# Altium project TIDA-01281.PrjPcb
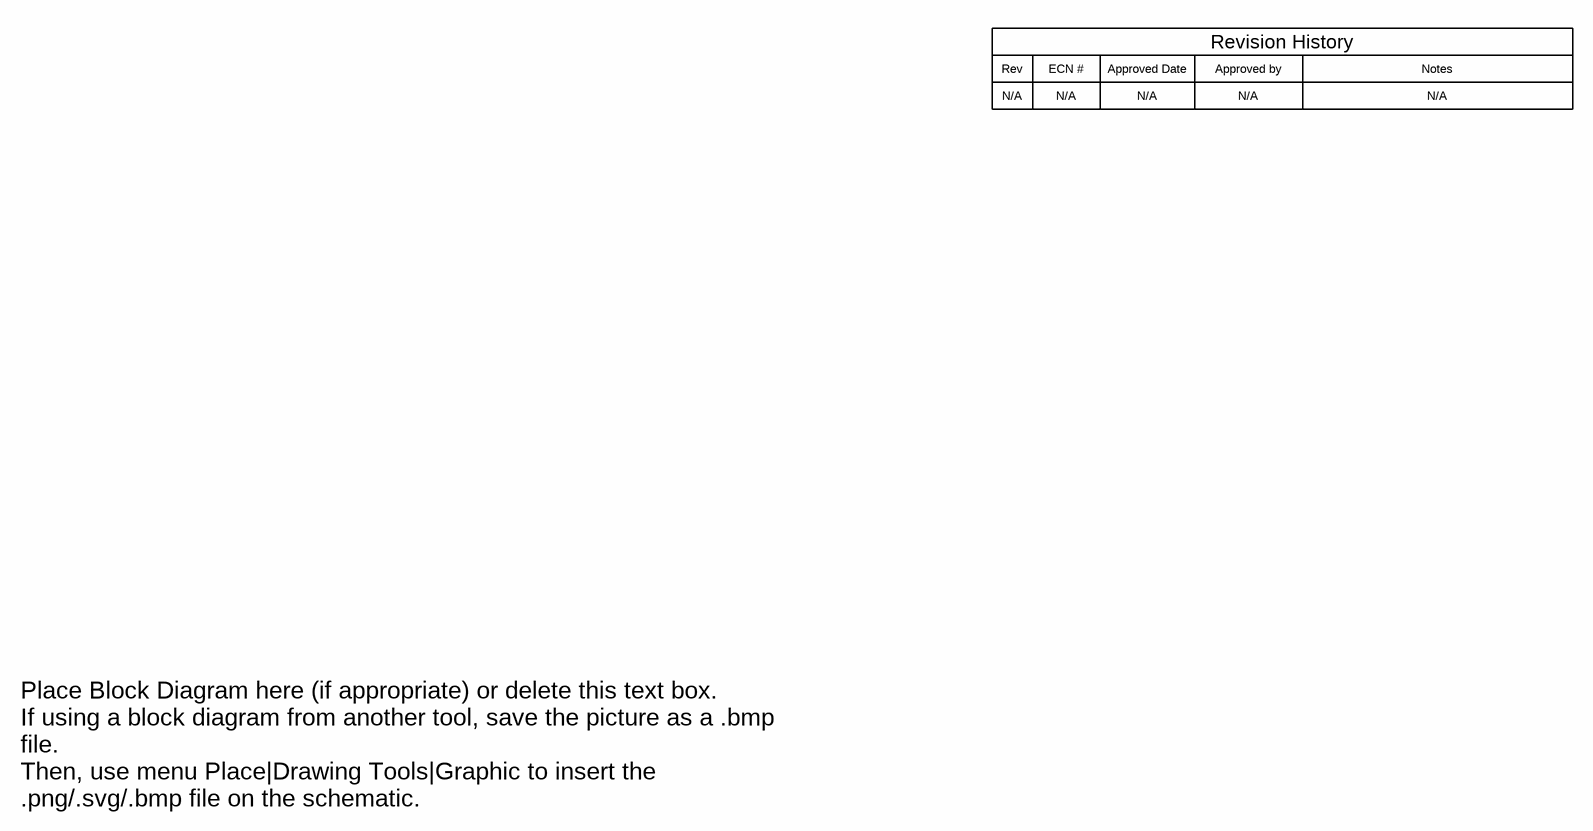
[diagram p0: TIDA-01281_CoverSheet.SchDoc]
TID: TIDA-01281; TechSupport: http://www.ti.com/support; SCH_Rev: E1; PRJ_Title: Communication Module; PRJ_Number: TIDA-01281; PRJ_Engineer: Ramkumar S; PRJ_Customer: Public Release; PCB_Rev: E1; PCB_Layout: Akshay Labhe; EVM_Orderable: N/A; CopyrightYear: 2016
3 sheets, 110 parts. Net scope: global (net labels, ports and power ports of the same name join across sheets).
Board file: TIDA-01281.PcbDoc
Sheets:
  TIDA-01281_CoverSheet.SchDoc
  TIDA-01281_Sheet1.SchDoc
  TIDA-01281_Hardware.SchDoc

## Sheet TIDA-01281_CoverSheet.SchDoc
size 431 x 279 mm; Date: Not shown in title block; ApprovedBy: Not shown in title block; CheckedBy: Not shown in title block; Author: Not shown in title block; CompanyName: Not shown in title block; DrawnBy: Ramkumar S; Engineer: Not shown in title block; Organization: Not shown in title block; Address1: Not shown in title block; Address2: Not shown in title block; Address3: Not shown in title block; Address4: Not shown in title block; DocumentNumber: 1; Revision: Use project parameter SCH_Rev; SheetNumber: 1; SheetTotal: 3; PageSetup: Record=PageOptions¦CenterHorizontal=True¦CenterVertical=True¦PrintScale=1.00¦XCorrection=1.00¦YCorrection=1.00¦PrintKind=0¦BorderSize=5000000¦LeftOffset=0¦BottomOffset=0¦Orientation=2¦PaperLength=1000¦PaperWidth=1000¦Scale=100¦PaperSource=15¦PrintQuality=600¦MediaType=1¦DitherType=10¦PaperKind=Letter¦PrintScaleMode=1

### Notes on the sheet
- Rev
- N/A
- ECN #
- Approved Date
- Approved by
- Revision History
- Notes
- Place Block Diagram here (if appropriate) or delete this text box.
  If using a block diagram from another tool, save the picture as a .bmp file.
  Then, use menu Place|Drawing Tools|Graphic to insert the .png/.svg/.bmp file on the schematic.

## Sheet TIDA-01281_Sheet1.SchDoc
size 431 x 279 mm; Date: Not shown in title block; ApprovedBy: Not shown in title block; CheckedBy: Not shown in title block; Author: Not shown in title block; CompanyName: Not shown in title block; DrawnBy: Ramkumar S; Engineer: Not shown in title block; Organization: Not shown in title block; Address1: Not shown in title block; Address2: Not shown in title block; Address3: Not shown in title block; Address4: Not shown in title block; DocumentNumber: 1; Revision: Use project parameter SCH_Rev; SheetNumber: 2; SheetTotal: 3; PageSetup: Record=PageOptions¦CenterHorizontal=True¦CenterVertical=True¦PrintScale=1.00¦XCorrection=1.00¦YCorrection=1.00¦PrintKind=0¦BorderSize=5000000¦LeftOffset=0¦BottomOffset=0¦Orientation=2¦PaperLength=1000¦PaperWidth=1000¦Scale=100¦PaperSource=15¦PrintQuality=600¦MediaType=1¦DitherType=10¦PaperKind=Letter¦PrintScaleMode=1
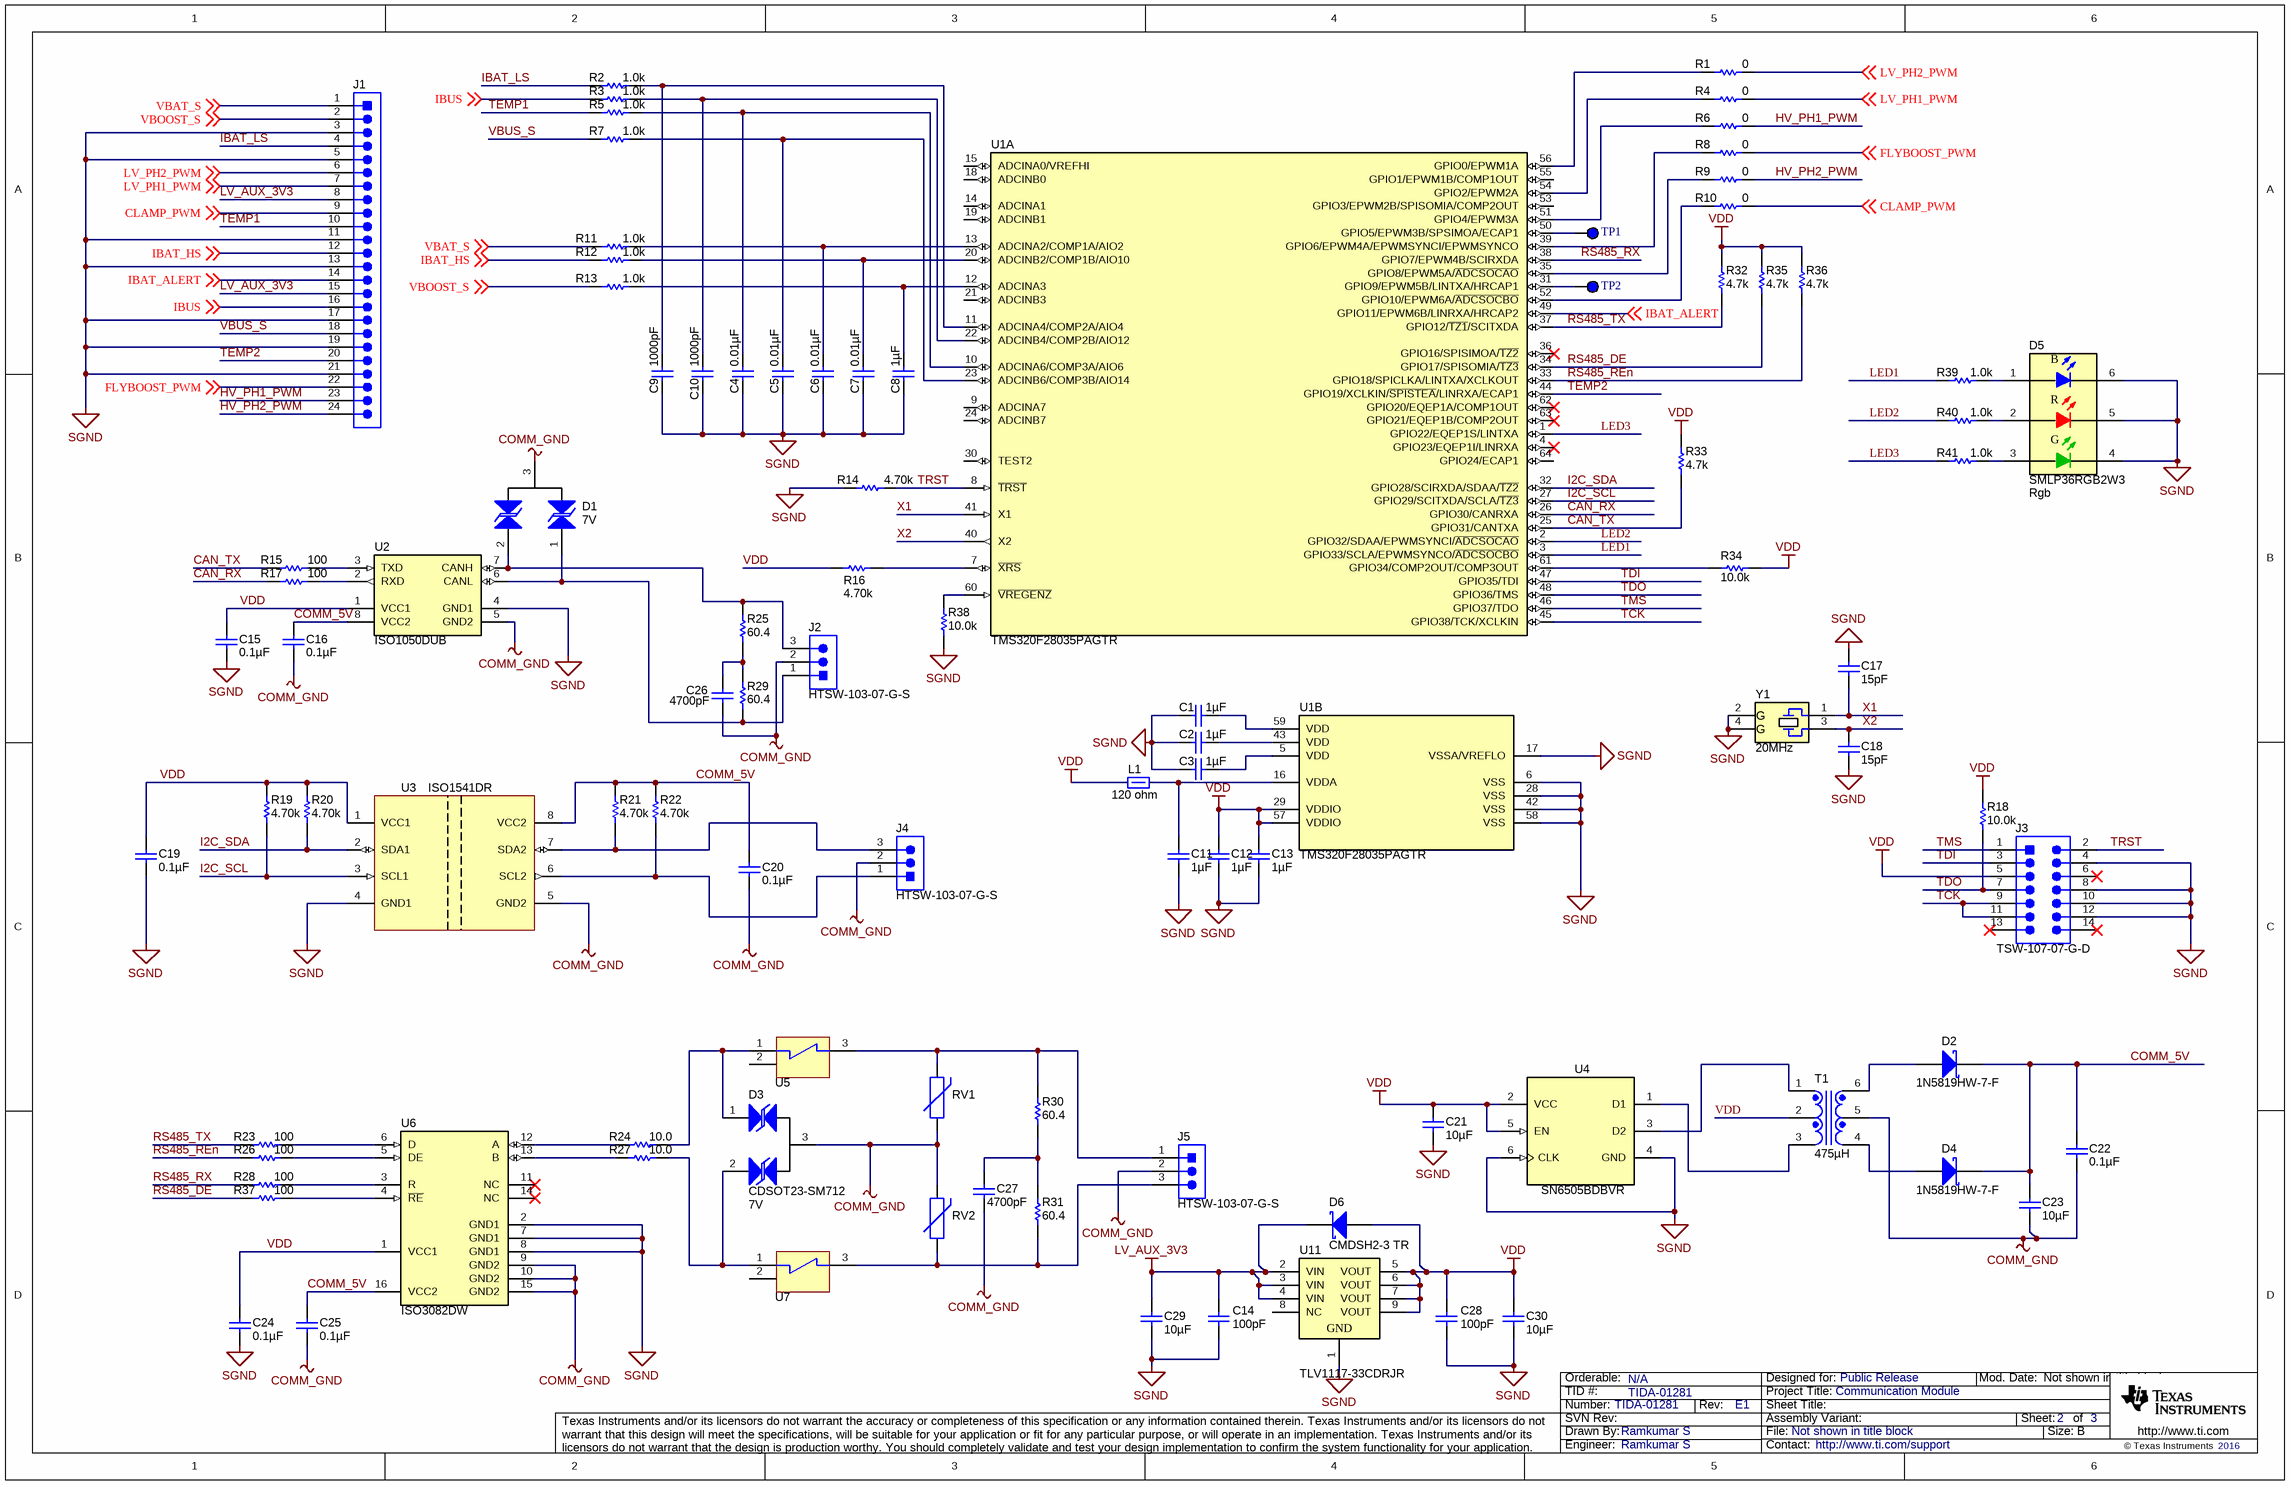
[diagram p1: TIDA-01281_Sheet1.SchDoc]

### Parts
C1  ValueDisplayed: 1µF  [0603]  (hidden comment: GRM188R70J105KA01D)
C2  ValueDisplayed: 1µF  [0603]  (hidden comment: GRM188R70J105KA01D)
C3  ValueDisplayed: 1µF  [0603]  (hidden comment: GRM188R70J105KA01D)
C4  ValueDisplayed: 0.01µF  [0603]  (hidden comment: 06031C103JAT2A)
C5  ValueDisplayed: 0.01µF  [0603]  (hidden comment: 06031C103JAT2A)
C6  ValueDisplayed: 0.01µF  [0603]  (hidden comment: 06031C103JAT2A)
C7  ValueDisplayed: 0.01µF  [0603]  (hidden comment: 06031C103JAT2A)
C8  ValueDisplayed: 1µF  [0603]  (hidden comment: GRM188R61H105KAALD)
C9  ValueDisplayed: 1000pF  [0603]  (hidden comment: 06031C102KAT2A)
C10  ValueDisplayed: 1000pF  [0603]  (hidden comment: 06031C102KAT2A)
C11  ValueDisplayed: 1µF  [0603]  (hidden comment: GRM188R70J105KA01D)
C12  ValueDisplayed: 1µF  [0603]  (hidden comment: GRM188R70J105KA01D)
C13  ValueDisplayed: 1µF  [0603]  (hidden comment: GRM188R70J105KA01D)
C14  ValueDisplayed: 100pF  [0603]  (hidden comment: 06035A101JAT2A)
C15  ValueDisplayed: 0.1µF  [0603]  (hidden comment: 06033C104JAT2A)
C16  ValueDisplayed: 0.1µF  [0603]  (hidden comment: 06033C104JAT2A)
C17  ValueDisplayed: 15pF  [0603]  (hidden comment: GRM1885C2A150JA01D)
C18  ValueDisplayed: 15pF  [0603]  (hidden comment: GRM1885C2A150JA01D)
C19  ValueDisplayed: 0.1µF  [0603]  (hidden comment: 06033C104JAT2A)
C20  ValueDisplayed: 0.1µF  [0603]  (hidden comment: 06033C104JAT2A)
C21  ValueDisplayed: 10µF  [0805_HV]  (hidden comment: GRM21BR61E106KA73L)
C22  ValueDisplayed: 0.1µF  [0603]  (hidden comment: 06035C104KAT2A)
C23  ValueDisplayed: 10µF  [0805_HV]  (hidden comment: GRM21BR61E106KA73L)
C24  ValueDisplayed: 0.1µF  [0603]  (hidden comment: 06033C104JAT2A)
C25  ValueDisplayed: 0.1µF  [0603]  (hidden comment: 06033C104JAT2A)
C26  ValueDisplayed: 4700pF  [0603]  (hidden comment: 06031C472JAT2A)
C27  ValueDisplayed: 4700pF  [0603]  (hidden comment: 06031C472JAT2A)
C28  ValueDisplayed: 100pF  [0603]  (hidden comment: 06035A101JAT2A)
C29  ValueDisplayed: 10µF  [0805_HV]  (hidden comment: GRM21BR61E106KA73L)
C30  ValueDisplayed: 10µF  [0805_HV]  (hidden comment: GRM21BR61E106KA73L)
D1  value 7V  [SOT-23]  (hidden comment: CDSOT23-SM712)
D2  1N5819HW-7-F  [SOD-123]
D3  CDSOT23-SM712  value 7V  [SOT-23]
D4  1N5819HW-7-F  [SOD-123]
D5  SMLP36RGB2W3  value Rgb  [PicoLED_RGB_150x100]
D6  CMDSH2-3 TR  [SOD-323]
J1  TSW-128-09-G-S-RE  [CONN_TSW-128-09-X-S-RE]  (value not drawn)
J2  HTSW-103-07-G-S  [Samtec_HTSW-103-07-G-S]
J3  TSW-107-07-G-D  [TSW-107-07-G-D]
J4  HTSW-103-07-G-S  [Samtec_HTSW-103-07-G-S]
J5  HTSW-103-07-G-S  [Samtec_HTSW-103-07-G-S]
L1  value 120 ohm  [0603]  (hidden comment: BLM18SG121TN1D)
R1  ValueDisplayed: 0  [0603]  (hidden comment: RC0603JR-070RL)
R2  ValueDisplayed: 1.0k  [0603]  (hidden comment: CRCW06031K00JNEA)
R3  ValueDisplayed: 1.0k  [0603]  (hidden comment: CRCW06031K00JNEA)
R4  ValueDisplayed: 0  [0603]  (hidden comment: RC0603JR-070RL)
R5  ValueDisplayed: 1.0k  [0603]  (hidden comment: CRCW06031K00JNEA)
R6  ValueDisplayed: 0  [0603]  (hidden comment: RC0603JR-070RL)
R7  ValueDisplayed: 1.0k  [0603]  (hidden comment: CRCW06031K00JNEA)
R8  ValueDisplayed: 0  [0603]  (hidden comment: RC0603JR-070RL)
R9  ValueDisplayed: 0  [0603]  (hidden comment: RC0603JR-070RL)
R10  ValueDisplayed: 0  [0603]  (hidden comment: RC0603JR-070RL)
R11  ValueDisplayed: 1.0k  [0603]  (hidden comment: CRCW06031K00JNEA)
R12  ValueDisplayed: 1.0k  [0603]  (hidden comment: CRCW06031K00JNEA)
R13  ValueDisplayed: 1.0k  [0603]  (hidden comment: CRCW06031K00JNEA)
R14  ValueDisplayed: 4.70k  [0603]  (hidden comment: RC0603FR-074K7L)
R15  ValueDisplayed: 100  [0603]  (hidden comment: CRCW0603100RFKEA)
R16  ValueDisplayed: 4.70k  [0603]  (hidden comment: RC0603FR-074K7L)
R17  ValueDisplayed: 100  [0603]  (hidden comment: CRCW0603100RFKEA)
R18  ValueDisplayed: 10.0k  [0603]  (hidden comment: RC0603FR-0710KL)
R19  ValueDisplayed: 4.70k  [0603]  (hidden comment: RC0603FR-074K7L)
R20  ValueDisplayed: 4.70k  [0603]  (hidden comment: RC0603FR-074K7L)
R21  ValueDisplayed: 4.70k  [0603]  (hidden comment: RC0603FR-074K7L)
R22  ValueDisplayed: 4.70k  [0603]  (hidden comment: RC0603FR-074K7L)
R23  ValueDisplayed: 100  [0603]  (hidden comment: CRCW0603100RFKEA)
R24  ValueDisplayed: 10.0  [0805_HV]  (hidden comment: CRT0805-BY-10R0ELF)
R25  ValueDisplayed: 60.4  [0805_HV]  (hidden comment: CRCW080560R4FKEA)
R26  ValueDisplayed: 100  [0603]  (hidden comment: CRCW0603100RFKEA)
R27  ValueDisplayed: 10.0  [0805_HV]  (hidden comment: CRT0805-BY-10R0ELF)
R28  ValueDisplayed: 100  [0603]  (hidden comment: CRCW0603100RFKEA)
R29  ValueDisplayed: 60.4  [0805_HV]  (hidden comment: CRCW080560R4FKEA)
R30  ValueDisplayed: 60.4  [0805_HV]  (hidden comment: CRCW080560R4FKEA)
R31  ValueDisplayed: 60.4  [0805_HV]  (hidden comment: CRCW080560R4FKEA)
R32  ValueDisplayed: 4.7k  [0603]  (hidden comment: CRCW06034K70JNEA)
R33  ValueDisplayed: 4.7k  [0603]  (hidden comment: CRCW06034K70JNEA)
R34  ValueDisplayed: 10.0k  [0603]  (hidden comment: RC0603FR-0710KL)
R35  ValueDisplayed: 4.7k  [0603]  (hidden comment: CRCW06034K70JNEA)
R36  ValueDisplayed: 4.7k  [0603]  (hidden comment: CRCW06034K70JNEA)
R37  ValueDisplayed: 100  [0603]  (hidden comment: CRCW0603100RFKEA)
R38  ValueDisplayed: 10.0k  [0603]  (hidden comment: RC0603FR-0710KL)
R39  ValueDisplayed: 1.0k  [0603]  (hidden comment: CRCW06031K00JNEA)
R40  ValueDisplayed: 1.0k  [0603]  (hidden comment: CRCW06031K00JNEA)
R41  ValueDisplayed: 1.0k  [0603]  (hidden comment: CRCW06031K00JNEA)
RV1  MOV-10D201K  [Bourns_MOV-10DxxxK]  (value not drawn)
RV2  MOV-10D201K  [Bourns_MOV-10DxxxK]  (value not drawn)
T1  ValueDisplayed: 475µH  [Wurth_760390013]  (hidden comment: 760390013)
TP1  5117  [Keystone5117]  (value not drawn)
TP2  5117  [Keystone5117]  (value not drawn)
U1  TMS320F28035PAGTR  [PAG0064A_N]  (parts A,B of 2)
U2  ISO1050DUB  [DUB0008A_N]
U3  ISO1541DR  [D0008A_N]
U4  SN6505BDBVR  [DBV0006A_N]
U5  TBU-CA065-200-WH  [TBU-CA]  (value not drawn)
U6  ISO3082DW  [DW0016A_N]
U7  TBU-CA065-200-WH  [TBU-CA]  (value not drawn)
U11  TLV1117-33CDRJR  [DRJ0008A]
Y1  Frequency: 20MHz  [XTAL_TXC-7B]  (hidden comment: 7B-20.000MEEQ-T)

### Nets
COMM_GND: C16.2 C20.2 C22.2 C23.1 C25.2 C26.1 C27.1 D1.3 D3.3 J2.2 J4.2 J5.2 RV1.1 RV2.2 T1.5 U2.5(GND2) U3.5(GND2) U6.9(GND2) U6.10(GND2) U6.15(GND2)
LV_AUX_3V3: C14.2 C29.1 D6.1(K) J1.8 J1.15 U11.2(VIN) U11.3(VIN) U11.4(VIN)
SGND: C1.2 C2.2 C3.2 C4.2 C5.2 C6.2 C7.2 C8.2 C9.2 C10.2 C11.1 C12.1 C13.1 C14.1 C15.2 C17.2 C18.2 C19.2 C21.2 C24.2 C28.1 C29.2 C30.2 D5.4 D5.5 D5.6 J1.3 J1.5 J1.11 J1.13 J1.17 J1.19 J1.21 J3.4 J3.8 J3.10 J3.12 R14.2 R38.2 U1.6(VSS) U1.17(VSSA/VREFLO) U1.28(VSS) U1.42(VSS) U1.58(VSS) U2.4(GND1) U3.4(GND1) U4.4(GND) U4.6(CLK) U6.2(GND1) U6.7(GND1) U6.8(GND1) U11.1(GND) Y1.2(GND) Y1.4(GND)
VDD: C12.2 C13.2 C15.1 C19.1 C21.1 C24.1 C28.2 C30.1 D6.2(A) J3.5 L1.1 R16.2 R18.2 R19.1 R20.1 R32.1 R33.1 R34.2 R35.1 R36.1 T1.2 U1.29(VDDIO) U1.57(VDDIO) U2.1(VCC1) U3.1(VCC1) U4.2(VCC) U4.5(EN) U6.1(VCC1) U11.5(VOUT) U11.6(VOUT) U11.7(VOUT) U11.9(VOUT)
CAN_RX: R17.1 U1.26(GPIO30/CANRXA)
CAN_TX: R15.1 R33.2 U1.25(GPIO31/CANTXA)
CLAMP_PWM: J1.9 R10.2 ; off-sheet CLAMP_PWM
COMM_5V: C16.1 C20.1 C22.1 C23.2 C25.1 D2.1(K) D4.1(K) R21.1 R22.1 U2.8(VCC2) U3.8(VCC2) U6.16(VCC2)
FLYBOOST_PWM: J1.22 R8.2 ; off-sheet FLYBOOST_PWM
HV_PH1_PWM: J1.23 R6.2
HV_PH2_PWM: J1.24 R9.2
I2C_SCL: R19.2 U1.27(GPIO29/SCITXDA/SCLA/~{TZ3}) U3.3(SCL1)
I2C_SDA: R20.2 U1.32(GPIO28/SCIRXDA/SDAA/~{TZ2}) U3.2(SDA1)
IBAT_ALERT: J1.14 U1.49(GPIO11/EPWM6B/LINRXA/HRCAP2) ; off-sheet IBAT_ALERT
IBAT_HS: J1.12 R12.1 ; off-sheet IBAT_HS
IBAT_LS: J1.4 R2.1
IBUS: J1.16 R3.1 ; off-sheet IBUS
LED1: R39.1 U1.3(GPIO33/SCLA/EPWMSYNCO/~{ADCSOCBO})
LED2: R40.1 U1.2(GPIO32/SDAA/EPWMSYNCI/~{ADCSOCAO})
LED3: R41.1 U1.1(GPIO22/EQEP1S/LINTXA)
LV_PH1_PWM: J1.7 R4.2 ; off-sheet LV_PH1_PWM
LV_PH2_PWM: J1.6 R1.2 ; off-sheet LV_PH2_PWM
RS485_DE: R35.2 R37.2 U1.34(GPIO17/SPISOMIA/~{TZ3})
RS485_REn: R26.2 R36.2 U1.33(GPIO18/SPICLKA/LINTXA/XCLKOUT)
RS485_RX: R28.2 U1.38(GPIO7/EPWM4B/SCIRXDA)
RS485_TX: R23.2 R32.2 U1.37(GPIO12/~{TZ1}/SCITXDA)
TCK: J3.9 J3.11 U1.45(GPIO38/TCK/XCLKIN)
TDI: J3.3 U1.47(GPIO35/TDI)
TDO: J3.7 R18.1 U1.48(GPIO36/TMS)
TEMP1: J1.10 R5.1
TEMP2: J1.20 U1.44(GPIO19/XCLKIN/~{SPISTEA}/LINRXA/ECAP1)
TMS: J3.1 U1.46(GPIO37/TDO)
TRST: J3.2 R14.1 U1.8(~{TRST})
VBAT_S: J1.1 R11.1 ; off-sheet VBAT_S
VBOOST_S: J1.2 R13.1 ; off-sheet VBOOST_S
VBUS_S: J1.18 R7.1
X1: C17.1 U1.41(X1) Y1.1
X2: C18.1 U1.40(X2) Y1.3
NetC1_1: C1.1 U1.59(VDD)
NetC2_1: C2.1 U1.43(VDD)
NetC3_1: C3.1 U1.5(VDD)
NetC4_1: C4.1 R5.2 U1.10(ADCINA6/COMP3A/AIO6)
NetC5_1: C5.1 R7.2 U1.23(ADCINB6/COMP3B/AIO14)
NetC6_1: C6.1 R11.2 U1.13(ADCINA2/COMP1A/AIO2)
NetC7_1: C7.1 R12.2 U1.20(ADCINB2/COMP1B/AIO10)
NetC8_1: C8.1 R13.2 U1.12(ADCINA3)
NetC9_1: C9.1 R2.2 U1.11(ADCINA4/COMP2A/AIO4)
NetC10_1: C10.1 R3.2 U1.22(ADCINB4/COMP2B/AIO12)
NetC11_2: C11.2 L1.2 U1.16(VDDA)
NetC26_2: C26.2 R25.2 R29.1
NetC27_2: C27.2 R30.2 R31.1
NetD1_1: D1.1 J2.1 R29.2 U2.6(CANL)
NetD1_2: D1.2 J2.3 R25.1 U2.7(CANH)
NetD2_2: D2.2(A) T1.6
NetD3_1: D3.1 R24.2 U5.1(Line_In/Out)
NetD3_2: D3.2 R27.2 U7.1(Line_In/Out)
NetD4_2: D4.2(A) T1.4
NetD5_1: D5.1(A) R39.2
NetD5_2: D5.2 R40.2
NetD5_3: D5.3 R41.2
NetJ4_1: J4.1 R22.2 U3.6(SCL2)
NetJ4_3: J4.3 R21.2 U3.7(SDA2)
NetJ5_1: J5.1 R30.1 RV1.2 U5.3(Line_Out/In)
NetJ5_3: J5.3 R31.2 RV2.1 U7.3(Line_Out/In)
NetR1_1: R1.1 U1.56(GPIO0/EPWM1A)
NetR4_1: R4.1 U1.54(GPIO2/EPWM2A)
NetR6_1: R6.1 U1.51(GPIO4/EPWM3A)
NetR8_1: R8.1 U1.39(GPIO6/EPWM4A/EPWMSYNCI/EPWMSYNCO)
NetR9_1: R9.1 U1.35(GPIO8/EPWM5A/~{ADCSOCAO})
NetR10_1: R10.1 U1.52(GPIO10/EPWM6A/~{ADCSOCBO})
NetR15_2: R15.2 U2.3(TXD)
NetR16_1: R16.1 U1.7(~{XRS})
NetR17_2: R17.2 U2.2(RXD)
NetR23_1: R23.1 U6.6(D)
NetR24_1: R24.1 U6.12(A)
NetR26_1: R26.1 U6.5(DE)
NetR27_1: R27.1 U6.13(B)
NetR28_1: R28.1 U6.3(R)
NetR34_1: R34.1 U1.61(GPIO34/COMP2OUT/COMP3OUT)
NetR37_1: R37.1 U6.4(~{RE})
NetR38_1: R38.1 U1.60(~{VREGENZ})
NetT1_1: T1.1 U4.3(D2)
NetT1_3: T1.3 U4.1(D1)
NetTP1_1: TP1.1 U1.50(GPIO5/EPWM3B/SPSIMOA/ECAP1)
NetTP2_1: TP2.1 U1.31(GPIO9/EPWM5B/LINTXA/HRCAP1)

Not connected (* = marked no-connect by the designer): J3 6* 13* 14*; U1 4(GPIO23/EQEP1I/LINRXA)* 9(ADCINA7) 14(ADCINA1) 15(ADCINA0/VREFHI) 18(ADCINB0) 19(ADCINB1) 21(ADCINB3) 24(ADCINB7) 30(TEST2) 36(GPIO16/SPISIMOA/~{TZ2})* 53(GPIO3/EPWM2B/SPISOMIA/COMP2OUT) 55(GPIO1/EPWM1B/COMP1OUT) 62(GPIO20/EQEP1A/COMP1OUT)* 63(GPIO21/EQEP1B/COMP2OUT)* 64(GPIO24/ECAP1); U5 2(NU); U6 11(NC)* 14(NC)*; U7 2(NU); U11 8(NC)

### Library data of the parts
C1-C3 C11-C13 = GRM188R70J105KA01D: CAP, CERM, 1 µF, 6.3 V, +/- 10%, X7R, 0603; Manufacturer: MuRata; Polarized: N; CompType: Capacitor; Value: 1uF; U/M: EA; Cap_F: 0.000001; Tolerance_%: 10; Value1: Unknown; VDC_V: 6.3; Value2: 6.3V; TaMin_C: -55; TaMax_C: 125; AEC Category: Q200
C4-C7 = 06031C103JAT2A: CAP, CERM, 0.01 µF, 100 V, +/- 5%, X7R, 0603; Manufacturer: AVX; Polarized: N; CompType: Capacitor; Value: 0.01uF; U/M: EA; Cap_F: 0.00000001; Tolerance_%: 5; ESR_ohm: 0.098; Value1: 0.098 ohm; VDC_V: 100; Value2: 100V; TaMin_C: -55; TaMax_C: 125
C8 = GRM188R61H105KAALD: CAP, CERM, 1 µF, 50 V, +/- 10%, X5R, 0603; Manufacturer: MuRata; Polarized: N; CompType: Capacitor; Value: 1uF; U/M: EA; Cap_F: 0.000001; Tolerance_%: 10; Value1: Unknown; VDC_V: 50; Value2: 50V; TaMin_C: -55; TaMax_C: 85; AEC Category: Q200
C9 C10 = 06031C102KAT2A: CAP, CERM, 1000 pF, 100 V, +/- 10%, X7R, 0603; Manufacturer: AVX; Polarized: N; CompType: Capacitor; Value: 1000pF; U/M: EA; Cap_F: 0.000000001; Tolerance_%: 10; ESR_ohm: 0.276; Value1: 0.276 ohm; VDC_V: 100; Value2: 100V; TaMin_C: -55; TaMax_C: 125
C14 C28 = 06035A101JAT2A: CAP, CERM, 100 pF, 50 V, +/- 5%, C0G/NP0, 0603; Manufacturer: AVX; Polarized: N; CompType: Capacitor; Value: 100pF; U/M: EA; Cap_F: 0.0000000001; Tolerance_%: 5; ESR_ohm: 0.119; Value1: 0.119 ohm; VDC_V: 50; Value2: 50V; TaMin_C: -55; TaMax_C: 125; SizeArea_mm2: 1.28; SizeAreaWB_mm2: 4.68; SizeX_mm: 1.6; SizeY_mm: 0.8; SizeZ_mm: 1; AEC Category: Q200
C15 C16 C19 C20 C24 C25 = 06033C104JAT2A: CAP, CERM, 0.1 µF, 25 V, +/- 5%, X7R, 0603; Manufacturer: AVX; Polarized: N; CompType: Capacitor; Value: 0.1uF; U/M: EA; Cap_F: 0.0000001; Tolerance_%: 5; ESR_ohm: 0.05; Value1: 0.05 ohm; VDC_V: 25; Value2: 25V; TaMin_C: -55; TaMax_C: 125
C17 C18 = GRM1885C2A150JA01D: CAP, CERM, 15 pF, 100 V, +/- 5%, C0G/NP0, 0603; Manufacturer: MuRata; Polarized: N; CompType: Capacitor; Value: 15pF; U/M: EA; Cap_F: 0.000000000015; Tolerance_%: 5; Value1: Unknown; VDC_V: 100; Value2: 100V; TaMin_C: -55; TaMax_C: 125
C21 C23 C29 C30 = GRM21BR61E106KA73L: CAP, CERM, 10 µF, 25 V, +/- 10%, X5R, 0805; Manufacturer: MuRata; Polarized: N; CompType: Capacitor; Value: 10uF; U/M: EA; Cap_F: 0.00001; Tolerance_%: 10; Value1: Unknown; VDC_V: 25; Value2: 25V; TaMin_C: -55; TaMax_C: 85; Cap_Case: 0805; AEC Category: Q200
C22 = 06035C104KAT2A: CAP, CERM, 0.1 µF, 50 V, +/- 10%, X7R, 0603; Manufacturer: AVX; Polarized: N; CompType: Capacitor; Value: 0.1uF; U/M: EA; Cap_F: 0.0000001; Tolerance_%: 10; Value1: Unknown; VDC_V: 50; Value2: 50V; TaMin_C: -55; TaMax_C: 125; AEC Category: Q200
C26 C27 = 06031C472JAT2A: CAP, CERM, 4700 pF, 100 V, +/- 5%, X7R, 0603; Manufacturer: AVX; Polarized: N; CompType: Capacitor; Value: 4700pF; U/M: EA; Cap_F: 0.0000000047; Tolerance_%: 5; ESR_ohm: 0.136; Value1: 0.136 ohm; VDC_V: 100; Value2: 100V; TaMin_C: -55; TaMax_C: 125; SizeArea_mm2: 1.28; SizeAreaWB_mm2: 4.68; SizeX_mm: 1.6; SizeY_mm: 0.8; SizeZ_mm: 1; AEC Category: Q200
D1 D3 = CDSOT23-SM712: Diode, TVS, Bi, 7 V, 400 W, SOT-23; Manufacturer: Bourns; SymbolCreator: a0411947; U/M: EA; Power_W: 400; Vr_V: 7; Value1: 400W
D2 D4 = 1N5819HW-7-F: Diode, Schottky, 40 V, 1 A, SOD-123; Manufacturer: Diodes Inc.; U/M: EA; Vf_V: 0.45; Value: 40V; Value1: 1A; Value2: 0.45V; Io_A: 1; Vr_V: 40; TJmax_C: 125; SizeAreaWB_mm2: 13.095; SizeArea_mm2: 6.545; SizeX_mm: 3.85; SizeY_mm: 1.7; SizeZ_mm: 1.35; AEC Category: Q101
D5 = SMLP36RGB2W3: LED, Rgb, SMD; Manufacturer: Rohm; SymbolCreator: Altium; Vf_V: 3.1; Value2: 3.1V; Io_A: 0.005; Vr_V: 5; Ir_A: 1e-005; Tjmax_C: 85; Value1: W; U/M: EA
D6 = CMDSH2-3 TR: Diode, Schottky, 30 V, 0.2 A, SOD-323; Manufacturer: Central Semiconductor; U/M: EA; Vf_V: 0.55; Value: 30V; Value1: 0.2A; Value2: 0.55V; Io_A: 0.2; Vr_V: 30; TJmax_C: 150; SizeAreaWB_mm2: 8.695; SizeArea_mm2: 3.645; SizeX_mm: 2.7; SizeY_mm: 1.35; SizeZ_mm: 1; AEC Category: Q101
J1 = TSW-128-09-G-S-RE: Header, 100mil, 28x1, Gold, R/A, TH; Manufacturer: Samtec; SymbolCreator: a0412235; Pitch_mm: 2.54; Gender: Male; Shrouded: N; Row_Count: 1; Current_A: 6.3; Voltage_V: 550; Cert_CSA: Y
J2 J4 J5 = HTSW-103-07-G-S: Header, 100mil, 3x1, Gold, TH; Manufacturer: Samtec; SymbolCreator: a0799628
J3 = TSW-107-07-G-D: Header, 100mil, 7x2, Gold, TH; Manufacturer: Samtec; SymbolCreator: a0412235; Pitch_mm: 2.54; Gender: Male; Shrouded: N; Row_Count: 2; Current_A: 6.3; Voltage_V: 550; Cert_CSA: Y
L1 = BLM18SG121TN1D: Ferrite Bead, 120 ohm @ 100 MHz, 3 A, 0603; Manufacturer: MuRata; Imax_A: 3; DCR_ohm: 0.025; Value1: 0.025 ohm; Value2: 3A; ZTyp@100MHz_Ohm: 120
R1 R4 R6 R8-R10 = RC0603JR-070RL: RES, 0, 5%, 0.1 W, 0603; Manufacturer: Yageo America; CompType: Resistor; Value: 0; Value_Code: 0000; Tolerance_%: 5; Power_W: 0.1; Value2: 0.1W; VDC_V: 50; TempCo: 200 ppm/C; EIA_Code: E24; U/M: EA
R2 R3 R5 R7 R11-R13 R39-R41 = CRCW06031K00JNEA: RES, 1.0 k, 5%, 0.1 W, 0603; Manufacturer: Vishay-Dale; CompType: Resistor; Value: 1.0k; Res_ohm: 1000; Value_Code: 1k00; Tolerance_%: 5; Power_W: 0.1; Value2: 0.1W; VDC_V: 75; TempCo: 200 ppm/C; EIA_Code: E24; U/M: EA
R14 R16 R19-R22 = RC0603FR-074K7L: RES, 4.70 k, 1%, 0.1 W, 0603; Manufacturer: Yageo America; CompType: Resistor; Value: 4.70k; Res_ohm: 4700; Value_Code: 4k70; Tolerance_%: 1; Power_W: 0.1; Value2: 0.1W; VDC_V: 150; TempCo: 200 ppm/C; U/M: EA
R15 R17 = CRCW0603100RFKEA: RES, 100, 1%, 0.1 W, 0603; Manufacturer: Vishay-Dale; CompType: Resistor; Value: 100; Value_Code: 100R; Tolerance_%: 1; Power_W: 0.1; Value2: 0.1W; VDC_V: 75; TempCo: 100 ppm/C; EIA_Code: E96; U/M: EA
R18 R34 R38 = RC0603FR-0710KL: RES, 10.0 k, 1%, 0.1 W, 0603; Manufacturer: Yageo America; CompType: Resistor; Value: 10.0k; Res_ohm: 10000; Value_Code: 10k0; Tolerance_%: 1; Power_W: 0.1; Value2: 0.1W; VDC_V: 150; TempCo: 200 ppm/C; EIA_Code: E96; U/M: EA
R23 R26 R28 R37 = CRCW0603100RFKEA: RES, 100, 1%, 0.1 W, 0603; Manufacturer: Vishay-Dale; CompType: Resistor; Value: 100; Value_Code: 100R; Tolerance_%: 1; Power_W: 0.1; Value2: 0.1W; VDC_V: 75; TempCo: 100 ppm/C; SizeArea_mm2: 1.28; SizeX_mm: 1.6; SizeY_mm: 0.8; EIA_Code: E96; U/M: EA; AEC Category: Q200
R24 R27 = CRT0805-BY-10R0ELF: RES, 10.0, 0.1%, 0.1 W, 0805; Manufacturer: Bourns; CompType: Resistor; Value: 10.0; Res_ohm: 10; Value_Code: 10R0; Tolerance_%: 0.1; Value2: 0.1W; VDC_V: 100; TempCo: 25 ppm/C; EIA_Code: E192; U/M: EA
R25 R29-R31 = CRCW080560R4FKEA: RES, 60.4, 1%, 0.125 W, 0805; Manufacturer: Vishay-Dale; CompType: Resistor; Value: 60.4; Value_Code: 60R4; Tolerance_%: 1; Power_W: 0.125; Value2: 0.125W; VDC_V: 150; TempCo: 100 ppm/C; EIA_Code: E96; U/M: EA; AEC Category: Q200
R32 R33 R35 R36 = CRCW06034K70JNEA: RES, 4.7 k, 5%, 0.1 W, 0603; Manufacturer: Vishay-Dale; CompType: Resistor; Value: 4.7k; Res_ohm: 4700; Value_Code: 4k70; Tolerance_%: 5; Power_W: 0.1; Value2: 0.1W; VDC_V: 75; TempCo: 200 ppm/C; SizeArea_mm2: 1.28; SizeX_mm: 1.6; SizeY_mm: 0.8; SizeZ_mm: 1; EIA_Code: E24; U/M: EA; AEC Category: Q200
RV1 RV2 = MOV-10D201K: Metal Oxide Varistor, TH; Manufacturer: Bourns; SymbolCreator: a0412235; Value: 200V
T1 = 760390013: Transformer, 475 uH, SMT; Manufacturer: Wurth Elektronik; SymbolCreator: a0799628; Value: 475uH; Lp: 475; DCR_ohm: 0.32
TP1 TP2 = 5117: Test Point, Miniature, Blue, TH; Manufacturer: Keystone; CompType: Test Point Loop; U/M: EA; ContactFinish: Silver
U1 = TMS320F28035PAGTR: Piccolo(TM) Microcontrollers, PAG0064A; Manufacturer: Texas Instruments; SymbolCreator: a0412235; SizeArea_mm2: 144; SizeAreaWB_mm2: 196; SizeX_mm: 12; SizeZ_mm: 1.2; CompType: IC; U/M: EA
U2 = ISO1050DUB: Isolated CAN Transceiver, -55 to 105 degC, 8-pin SOP (DUB), Green (RoHS & no Sb/Br); Manufacturer: Texas Instruments; Alternate PartNumber: Equivalent; Drivers Per Package: 1; Isolated: Yes; Rating: Catalog
U3 = ISO1541DR: Low-Power Bidirectional I2C Isolators, D0008A; Manufacturer: Texas Instruments; SymbolCreator: a0411947; CompType: IC; U/M: EA
U4 = SN6505BDBVR: LOW-NOISE 1A TRANSFORMER DRIVERS FOR ISOLATED POWER SUPPLIES, DBV0006A; Alternate PartNumber: SN6505BDBVT; Manufacturer: Texas Instruments; SymbolCreator: Altium; SizeArea_mm2: 8.12; SizeAreaWB_mm2: 14.82; SizeX_mm: 2.8; SizeY_mm: 2.9; SizeZ_mm: 1.45; CompType: IC; U/M: EA
U5 U7 = TBU-CA065-200-WH: TBU-CA series TBU High-Speed Protectors, TBU-CA; Manufacturer: Bourns; SymbolCreator: x0208325
U6 = ISO3082DW: Isolated RS-485 Transceiver, 0.2 Mbps, 5 V, Half Duplex, -40 to 85 degC, 16-pin SOIC (DW), Green (RoHS & no Sb/Br); Manufacturer: Texas Instruments; Alternate PartNumber: Equivalent; # of TX/RX: 1 TX / 1 RX; Drivers Per Package: 1; Isolated: Yes; Number of Nodes: 256; Signaling Rate(Mbps): 0.2; Common Mode Range: -7 to 12; ESD(kV): 16; Fault Protection(V): -9 to 14; Fail Safe: Idle, Open, Short; ICC(Max)(mA): 15; Supply Voltage(s)(V): 5; Rating: Catalog
U11 = TLV1117-33CDRJR: LDO with 4.7 to 15 V Input and 3.3 V Output, 0 to 125 degC, 8-Pin SON (DRJ), Green (RoHS & no Sb/Br); Manufacturer: Texas Instruments; Alternate PartNumber: Equivalent; Iout(Max)(A): 0.8; Iq(Typ)(mA): 5; SubFamily: Single Channel LDO; Vin(Max)(V): 15; Vin(Min)(V): 4.7; Vout(Max)(V): 3.3
Y1 = 7B-20.000MEEQ-T: Crystal, 20.000MHz, 10pF, SMD; Manufacturer: TXC Corporation; SymbolCreator: a0412235; U/M: EA; TaMin_C: -20; TaMax_C: 70; Frequency Stability: ±10ppm

## Sheet TIDA-01281_Hardware.SchDoc
size 431 x 279 mm; Date: Not shown in title block; ApprovedBy: Not shown in title block; CheckedBy: Not shown in title block; Author: Not shown in title block; CompanyName: Not shown in title block; DrawnBy: Ramkumar S; Engineer: Not shown in title block; Organization: Not shown in title block; Address1: Not shown in title block; Address2: Not shown in title block; Address3: Not shown in title block; Address4: Not shown in title block; DocumentNumber: 1; Revision: Use project parameter SCH_Rev; SheetNumber: 3; SheetTotal: 3; PageSetup: Record=PageOptions¦CenterHorizontal=True¦CenterVertical=True¦PrintScale=1.00¦XCorrection=1.00¦YCorrection=1.00¦PrintKind=0¦BorderSize=5000000¦LeftOffset=0¦BottomOffset=0¦Orientation=2¦PaperLength=1000¦PaperWidth=1000¦Scale=100¦PaperSource=15¦PrintQuality=600¦MediaType=1¦DitherType=10¦PaperKind=Letter¦PrintScaleMode=1
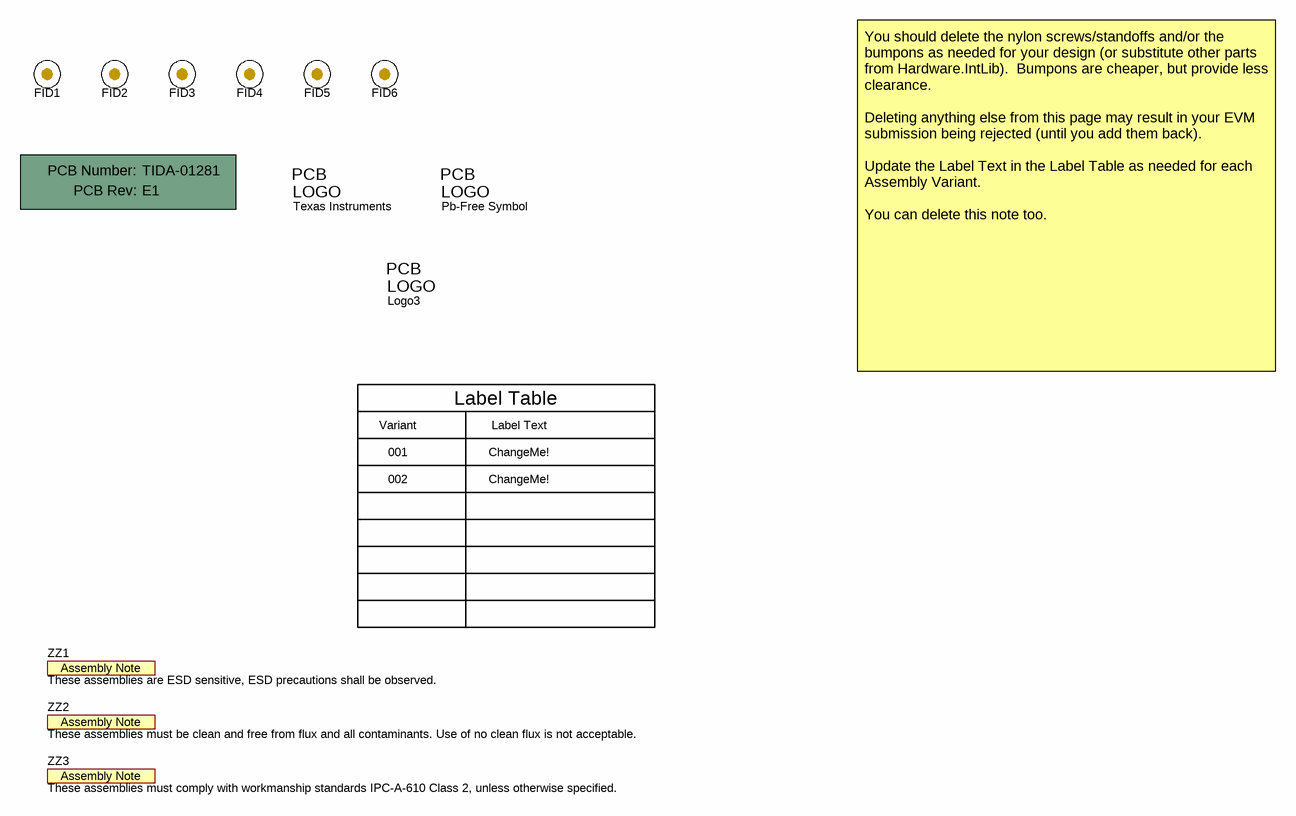
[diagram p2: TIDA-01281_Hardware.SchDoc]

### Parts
!PCB1  Printed Circuit Board  (value not drawn)  (mechanical)
FID1  Fiducial  [Fiducial10-20]  (value not drawn)
FID2  Fiducial  [Fiducial10-20]  (value not drawn)
FID3  Fiducial  [Fiducial10-20]  (value not drawn)
FID4  Fiducial  [Fiducial10-20]  (value not drawn)
FID5  Fiducial  [Fiducial10-20]  (value not drawn)
FID6  Fiducial  [Fiducial10-20]  (value not drawn)
Logo1  Texas Instruments  [TI_Stacked_Overlay_Small]  (no BOM)
Logo2  Pb-Free Symbol  [Pb-Free_Overlay_Small]  (no BOM)
Logo3  ESD Susceptible  [ESD_Overlay_Medium]  (value not drawn)  (no BOM)
ZZ1  These assemblies are ESD sensitive, ESD precautions shall be observed.  [AssemblyNote]  (no BOM)
ZZ2  These assemblies must be clean and free from flux and all contaminants. Use of no clean flux is not acceptable.  [AssemblyNote]  (no BOM)
ZZ3  These assemblies must comply with workmanship standards IPC-A-610 Class 2, unless otherwise specified.  [AssemblyNote]  (no BOM)

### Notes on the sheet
- Variant
- Label Table
- Label Text
- You should delete the nylon screws/standoffs and/or the bumpons as needed for your design (or substitute other parts from Hardware.IntLib).  Bumpons are cheaper, but provide less clearance.
  Deleting anything else from this page may result in your EVM submission being rejected (until you add them back).
  Update the Label Text in the Label Table as needed for each Assembly Variant.
  You can delete this note too.
- 001
- 002
- ChangeMe!

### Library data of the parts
!PCB1 = PCB: Manufacturer: Any; PartNumber: TIDA-01281; SymbolCreator: a0412235
FID1-FID6 = Fiducial: Fiducial mark.  There is nothing to buy or mount.; SymbolCreator: codlsc
Logo1 = TI_Logo: Texas Instrument Corporate Signature; SymbolCreator: codlsc
Logo2 = Pb-Free: SymbolCreator: a0412235
Logo3 = ESD_Susceptible: ESD Susceptible Symbol; SymbolCreator: a0412235
ZZ1-ZZ3 = AssemblyNote: SymbolCreator: codlsc

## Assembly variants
001: not fitted FID1 FID2 FID3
